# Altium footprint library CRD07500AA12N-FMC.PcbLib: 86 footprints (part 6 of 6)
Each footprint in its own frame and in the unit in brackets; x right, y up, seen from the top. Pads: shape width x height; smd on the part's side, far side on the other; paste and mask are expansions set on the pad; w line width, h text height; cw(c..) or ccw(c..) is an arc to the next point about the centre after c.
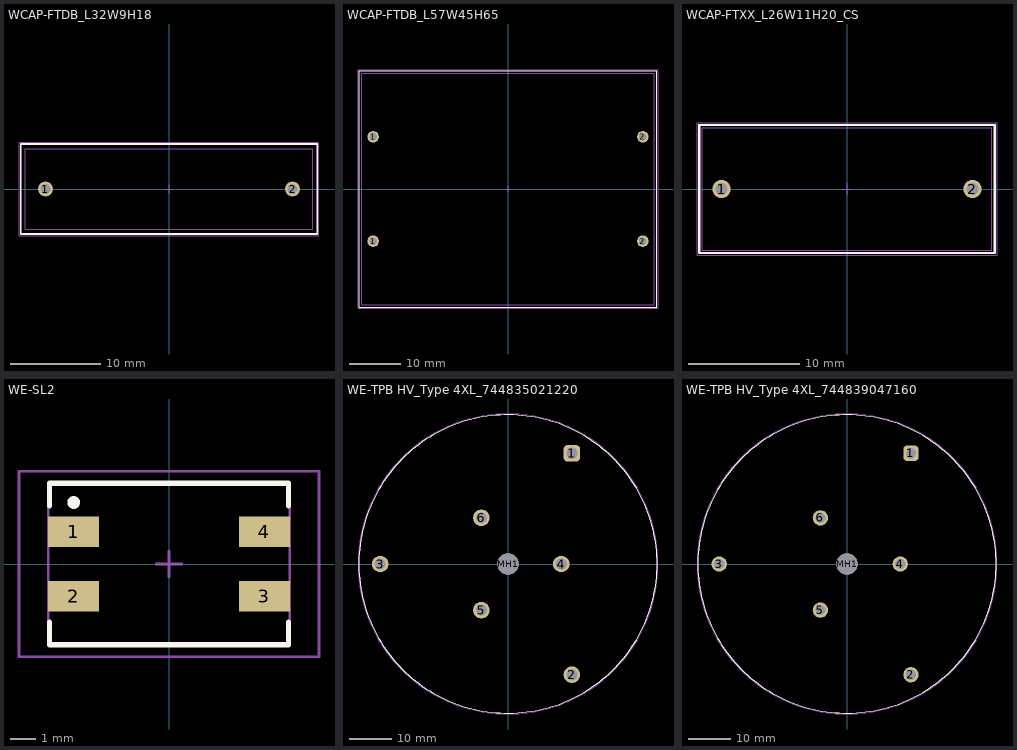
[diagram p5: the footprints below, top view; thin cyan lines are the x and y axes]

## WCAP-FTDB_L32W9H18 [mm] "Film Capacitor, THT, body 32.00x9.00mm"
height 18
pads (2):
  round 1.65 hole 1.1: 1(-13.75,0) 2(13.75,0)
Top Overlay:
  lines w0.2: -16.5,-5 -16.5,5 16.5,5 16.5,-5 -16.5,-5
Top 3D Body:
  lines w0.1: -16,-4.5 -16,4.5 16,4.5 16,-4.5 -16,-4.5
Top Courtyard:
  lines w0.05: -0.5,0 0.5,0 ; 0,-0.5 0,0.5 ; -16.7,-5.2 -16.7,5.2 16.7,5.2 16.7,-5.2 -16.7,-5.2
Top Component Outline:
  lines w0.1: -16,-4.5 -16,4.5 16,4.5 16,-4.5 -16,-4.5
Top Designator:
  text ".Designator" at -7.498,-0.5 h1.5
3D body "27,5x32x9x18.stp": height 18, standoff -4, extent -16,-4.5 16,4.5

## WCAP-FTDB_L57W45H65 [mm] "Film Capacitor, THT, body 57.00x45.00mm"
height 65
pads (4):
  round 2.25 hole 1.5: 1(-26.25,-10.15) 1(-26.25,10.15) 2(26.25,-10.15) 2(26.25,10.15)
Top Overlay:
  lines w0.2: -29,-23 -29,23 29,23 29,-23 -29,-23
Top 3D Body:
  lines w0.1: -28.5,-22.5 -28.5,22.5 28.5,22.5 28.5,-22.5 -28.5,-22.5
Top Courtyard:
  lines w0.05: -0.5,0 0.5,0 ; 0,-0.5 0,0.5 ; -29.2,-23.2 -29.2,23.2 29.2,23.2 29.2,-23.2 -29.2,-23.2
Top Component Outline:
  lines w0.1: -28.5,-22.5 -28.5,22.5 28.5,22.5 28.5,-22.5 -28.5,-22.5
Top Designator:
  text ".Designator" at -7.498,-0.5 h1.5
3D body "52,5x57x45x65.stp": height 65, standoff -4, extent -28.5,-22.5 28.5,22.5

## WCAP-FTXX_L26W11H20_CS [mm] "Film Capacitors, 26x11x20mm"
height 20
pads (2):
  round 1.65 hole 1.1: 1(-11.25,0) 2(11.25,0)
Top Overlay:
  lines w0.2: -13.25,-5.75 13.25,-5.75 13.25,5.75 -13.25,5.75 -13.25,-5.75
Top 3D Body:
  lines w0.1: -13,-5.5 -13,5.5 13,5.5 13,-5.5 -13,-5.5
Top Courtyard:
  lines w0.05: -0.5,0 0.5,0 ; 0,-0.5 0,0.5 ; -13.45,-5.95 13.45,-5.95 13.45,5.95 -13.45,5.95 -13.45,-5.95
Top Component Outline:
  lines w0.1: -13,-5.5 -13,5.5 13,5.5 13,-5.5 -13,-5.5
Top Designator:
  text ".Designator" at -7.498,-0.5 h1.5
3D body "22,5x26x20x11_CS.stp": height 20.05, standoff -3.95, extent -13,-5.5 13,5.5

## WE-SL2 [mm] "SMD Inductor, 4-Leads, Body 6.3 x 9.5 mm"
height 5.3
pads (4):
  rect 2x1.2 smd: 1(-3.75,1.27) 2(-3.75,-1.27) 3(3.75,-1.27) 4(3.75,1.27)
Top Overlay:
  circle w0.25: c-3.75,2.42 r0.125
  lines w0.2: -4.699,-2.286 -4.699,-3.175 ; -4.699,2.286 -4.699,3.175 4.699,3.175 4.699,2.286 ; 4.699,-2.286 4.699,-3.175 ; -4.699,-3.175 4.699,-3.175 ; -4.699,-3.175 4.699,-3.175 ; -4.699,-3.175 4.699,-3.175
Mechanical 13:
  lines w0.1: -4.75,-3.15 -4.75,3.15 4.75,3.15 4.75,-3.15 -4.75,-3.15
Mechanical 15:
  lines w0.1: -0.5,0 0.5,0 ; 0,-0.5 0,0.5 ; -5.9,-3.65 -5.9,3.65 5.9,3.65 5.9,-3.65 -5.9,-3.65
3D body "744229.stp": height 5, standoff 0, extent -4.6,-3 4.6,3

## WE-TPB HV_Type 4XL_744835021220 [mm] "Three-Phase Common Mode Power Line Choke, 6-Leads, body diameter 70mm"
height 39
pads (7):
  rrect50% 3.9x3.9 hole 2.6: 1(15,25.981)
  round 3.9 hole 2.6: 2(15,-25.981) 3(-30,0) 4(12.5,0) 5(-6.25,-10.825) 6(-6.25,10.825)
  round 5 hole 5 unplated: MH1(0,0)
Top Overlay:
  circle w0.2: c0,0 r35
Top 3D Body:
  circle w0.1: c0,0 r35
Top Courtyard:
  circle w0.05: c0,0 r35.2
  lines w0.05: -0.5,0 0.5,0 ; 0,-0.5 0,0.5
Top Assembly:
  circle w0.1: c0,0 r35
  text ".Designator" at -7.498,-0.5 h1.5
3D body "744835021220.stp": height 37.6, standoff -4.9, extent -34,-31.568 31.515,30.927

## WE-TPB HV_Type 4XL_744839047160 [mm] "Three-Phase Common Mode Power Line Choke, 6-Leads, body diameter 70mm"
height 39
pads (7):
  rrect50% 3.6x3.6 hole 2.4: 1(15,25.981)
  round 3.6 hole 2.4: 2(15,-25.981) 3(-30,0) 4(12.5,0) 5(-6.25,-10.825) 6(-6.25,10.825)
  round 5 hole 5 unplated: MH1(0,0)
Top Overlay:
  circle w0.2: c0,0 r35
Top 3D Body:
  circle w0.1: c0,0 r35
Top Courtyard:
  circle w0.05: c0,0 r35.2
  lines w0.05: -0.5,0 0.5,0 ; 0,-0.5 0,0.5
Top Assembly:
  circle w0.1: c0,0 r35
  text ".Designator" at -7.498,-0.5 h1.5
3D body "744839047160.stp": height 37.6, standoff -4.9, extent -34,-31.295 31.353,30.7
